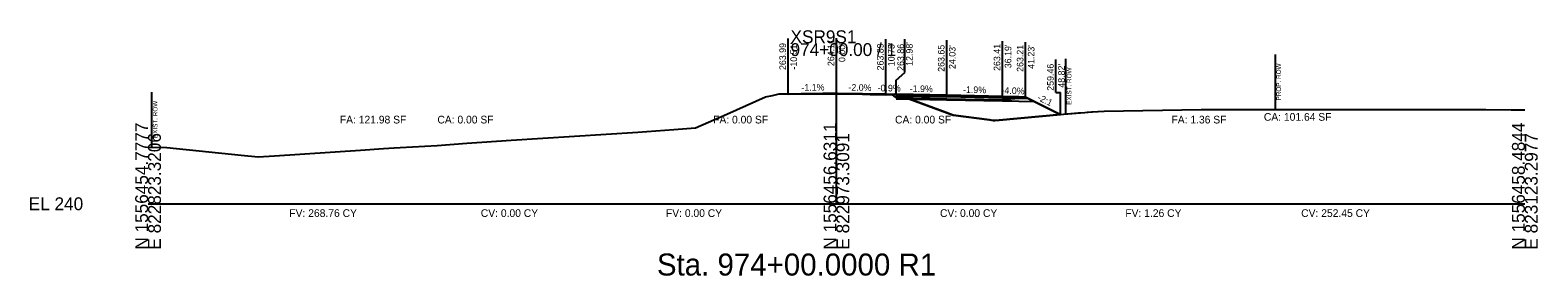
# Model space of a CAD drawing. Extents: x -26 to 823017, y -16 to 1558356.
# Drawn here: x 1974.3 to 2302.8, y 4984.3 to 5037.8 of the extents above; entities that cross this region are included whole.
import ezdxf

# ---------------------------------------------------------------- set-up
doc = ezdxf.new("R2010")
doc.units = 0
for name, color, linetype in [('ASPHALT_19MM1', 7, 'Continuous'), ('CONST_DCH', 7, 'Continuous'), ('CONST_LV3', 7, 'Continuous'), ('Draft_XS_Grid', 7, 'Continuous'), ('Draft_XS_Text', 7, 'Continuous'), ('DTM_CORRIDOR', 7, 'Continuous'), ('DTM_P_FINISHED_GRADE2', 7, 'Continuous'), ('DTM_X_GROUND', 7, 'Continuous'), ('SLOPE_STAKES_FILL', 7, 'Continuous'), ('X_PROFILES_1', 7, 'Continuous'), ('X_TRANS_EOP', 7, 'Continuous'), ('XS_CELL', 7, 'Continuous'), ('XS_P_ASPHALT', 7, 'Continuous'), ('XS_P_DR_GRAVEL', 7, 'Continuous'), ('XS_P_GROUND', 7, 'Continuous'), ('XS_P_NULL_POINT', 7, 'Continuous'), ('XS_P_ROW', 7, 'Continuous'), ('XS_P_SHOULDER', 7, 'Continuous'), ('XS_P_SUBGRADE_GRANULAR', 7, 'Continuous'), ('XS_P_SUBGRADE_LEVELING', 7, 'Continuous'), ('XS_P_SUBGRADE_MILLING', 7, 'Continuous'), ('XS_P_SUBGRADE_UNDERCUT', 7, 'Continuous'), ('XS_P_TX_CLEARZONE', 7, 'Continuous'), ('XS_P_TX_FS_BS', 7, 'Continuous'), ('XS_SHEET_EW_TX_AREA', 7, 'Continuous'), ('XS_SHEET_EW_TX_VOLUME', 7, 'Continuous'), ('XS_X_ROW', 7, 'Continuous')]:
    doc.layers.add(name, color=color, linetype=linetype)

msp = doc.modelspace()

# ---------------------------------------------------------------- linework, layer by layer
at = {"layer": 'ASPHALT_19MM1'}
for points in [[(2162.98, 5023.69), (2162.98, 5023.48), (2174.03, 5023.27), (2174.03, 5023.48), (2162.98, 5023.69)], [(2186.19, 5023.24), (2186.19, 5023.03), (2174.03, 5023.27), (2174.03, 5023.27), (2174.03, 5023.48), (2174.03, 5023.48), (2186.19, 5023.24)]]:
    msp.add_lwpolyline(points, dxfattribs=at)
at = {"layer": 'CONST_LV3'}
for points in [[(2000, 5012.33), (2000, 5012.33), (2004.12, 5012.29), (2020.27, 5010.59), (2024.02, 5010.19), (2027.53, 5010.43), (2046.28, 5011.68), (2051.29, 5012.02), (2053.61, 5012.17), (2054.95, 5012.26), (2063.03, 5012.73), (2069.48, 5013.21), (2072.7, 5013.42), (2079.12, 5013.85), (2106.7, 5015.57), (2114.6, 5016.17), (2119.29, 5016.52), (2126.13, 5019.55), (2134.53, 5023.27), (2136.05, 5023.63), (2137.52, 5023.96), (2139.49, 5023.99), (2139.49, 5023.99)], [(2150, 5024.11), (2164, 5023.83)], [(2160.75, 5023.79), (2160.75, 5023.79), (2162.11, 5023.75), (2162.11, 5023.75), (2162.11, 5023.75), (2162.11, 5023.75), (2162.12, 5023.74), (2162.16, 5023.71), (2162.44, 5023.5), (2162.52, 5023.45), (2162.98, 5023.11), (2162.98, 5023.11), (2174.03, 5022.9), (2174.03, 5022.9), (2186.19, 5022.66), (2187.06, 5022.76), (2189.76, 5023.05), (2190.83, 5023.16), (2191.23, 5023.21), (2192.94, 5022.35), (2198.76, 5019.46), (2198.78, 5019.46), (2198.82, 5019.46), (2199.47, 5019.52), (2200.29, 5019.6), (2202.66, 5019.79), (2204.15, 5019.91), (2204.6, 5019.95), (2205.59, 5020.03), (2205.79, 5020.05), (2208.33, 5020.17), (2229.48, 5020.51), (2274.71, 5020.55), (2291.51, 5020.53), (2297.01, 5020.5), (2300, 5020.47)], [(2162.75, 5023.88), (2164, 5023.83), (2164, 5023.83)], [(2191.25, 5023.2), (2198.81, 5019.46)]]:
    msp.add_lwpolyline(points, dxfattribs=at)
at = {"layer": 'DTM_P_FINISHED_GRADE2'}
msp.add_lwpolyline([(2139.49, 5023.99), (2150, 5024.11), (2160.75, 5023.96)], dxfattribs=at)
at = {"layer": 'DTM_X_GROUND'}
for points in [[(2000, 5012.33), (2000, 5012.33), (2004.12, 5012.29), (2020.27, 5010.59), (2024.02, 5010.19), (2027.53, 5010.43), (2046.28, 5011.68), (2051.29, 5012.02), (2053.61, 5012.17), (2054.95, 5012.26), (2063.03, 5012.73), (2069.48, 5013.21), (2072.7, 5013.42), (2079.12, 5013.85), (2106.7, 5015.57), (2114.6, 5016.17), (2119.29, 5016.52), (2126.13, 5019.55), (2134.53, 5023.27), (2136.05, 5023.63), (2137.52, 5023.96), (2147.12, 5024.07), (2150.24, 5024.11), (2155.68, 5024), (2157.37, 5023.97), (2162.98, 5023.86), (2163.19, 5023.79), (2164.22, 5023.48), (2173.94, 5019.86), (2175.45, 5019.29), (2183.36, 5018.29), (2184.15, 5018.18), (2184.49, 5018.14), (2185.48, 5018.23), (2199.47, 5019.53), (2204.15, 5019.91), (2205.59, 5020.04), (2208.33, 5020.17), (2229.48, 5020.51), (2274.71, 5020.55), (2291.51, 5020.53), (2297.01, 5020.5), (2300, 5020.47)], [(2000, 5012.33), (2000, 5012.33), (2004.12, 5012.29), (2020.27, 5010.59), (2024.02, 5010.19), (2027.53, 5010.43), (2046.28, 5011.68), (2051.29, 5012.02), (2053.61, 5012.17), (2054.95, 5012.26), (2063.03, 5012.73), (2069.48, 5013.21), (2072.7, 5013.42), (2079.12, 5013.85), (2106.7, 5015.57), (2114.6, 5016.17), (2119.29, 5016.52), (2126.13, 5019.55), (2134.53, 5023.27), (2136.05, 5023.63), (2137.52, 5023.96), (2147.12, 5024.07), (2150.24, 5024.11), (2155.68, 5023.96), (2157.37, 5023.91), (2162.11, 5023.75), (2162.11, 5023.75), (2162.11, 5023.75), (2162.11, 5023.75), (2162.12, 5023.74), (2162.16, 5023.71), (2162.44, 5023.5), (2162.52, 5023.45), (2162.98, 5023.11), (2162.98, 5023.11), (2174.03, 5022.9), (2174.03, 5022.9), (2186.19, 5022.66), (2187.06, 5022.76), (2189.76, 5023.05), (2190.83, 5023.16), (2191.23, 5023.21), (2192.94, 5022.35), (2198.76, 5019.46), (2198.78, 5019.46), (2198.82, 5019.46), (2199.47, 5019.52), (2200.29, 5019.6), (2202.66, 5019.79), (2204.15, 5019.91), (2204.6, 5019.95), (2205.59, 5020.03), (2205.79, 5020.05), (2208.33, 5020.17), (2229.48, 5020.51), (2274.71, 5020.55), (2291.51, 5020.53), (2297.01, 5020.5), (2300, 5020.47)], [(2000, 5012.33), (2000, 5012.33), (2004.12, 5012.29), (2020.27, 5010.59), (2024.02, 5010.19), (2027.53, 5010.43), (2046.28, 5011.68), (2051.29, 5012.02), (2053.61, 5012.17), (2054.95, 5012.26), (2063.03, 5012.73), (2069.48, 5013.21), (2072.7, 5013.42), (2079.12, 5013.85), (2106.7, 5015.57), (2114.6, 5016.17), (2119.29, 5016.52), (2126.13, 5019.55), (2134.53, 5023.27), (2136.05, 5023.63), (2137.52, 5023.96), (2139.49, 5023.99), (2139.49, 5023.99), (2150, 5024.11), (2150, 5024.11), (2150, 5024.11), (2150, 5024.11), (2150, 5024.11), (2150, 5024.11), (2150, 5024.11), (2150, 5024.11), (2160.75, 5023.96), (2160.75, 5023.96), (2160.75, 5023.96), (2162.11, 5023.75), (2162.11, 5023.75), (2162.11, 5023.75), (2162.11, 5023.75), (2162.12, 5023.74), (2162.16, 5023.71), (2162.44, 5023.5), (2162.52, 5023.45), (2162.98, 5023.11), (2162.98, 5023.11), (2174.03, 5022.9), (2174.03, 5022.9), (2186.19, 5022.66), (2187.06, 5022.76), (2189.76, 5023.05), (2190.83, 5023.16), (2191.23, 5023.21), (2192.94, 5022.35), (2198.76, 5019.46), (2198.78, 5019.46), (2198.82, 5019.46), (2199.47, 5019.52), (2200.29, 5019.6), (2202.66, 5019.79), (2204.15, 5019.91), (2204.6, 5019.95), (2205.59, 5020.03), (2205.79, 5020.05), (2208.33, 5020.17), (2229.48, 5020.51), (2274.71, 5020.55), (2291.51, 5020.53), (2297.01, 5020.5), (2300, 5020.47)]]:
    msp.add_lwpolyline(points, dxfattribs=at)
at = {"layer": 'X_TRANS_EOP'}
for points in [[(2162.98, 5023.86), (2162.98, 5023.69), (2174.03, 5023.48), (2174.03, 5023.65), (2162.98, 5023.86)], [(2186.19, 5023.41), (2186.19, 5023.24), (2174.03, 5023.48), (2174.03, 5023.48), (2174.03, 5023.65), (2174.03, 5023.65), (2186.19, 5023.41)]]:
    msp.add_lwpolyline(points, dxfattribs=at)
at = {"layer": 'XS_CELL'}
for p, q in [((2150, 5000), (2150, 5035)), ((2000, 5000), (2150, 5000)), ((2150, 5000), (2300, 5000))]:
    msp.add_line(p, q, dxfattribs=at)
at = {"layer": 'XS_P_ASPHALT'}
msp.add_lwpolyline([(2139.49, 5023.99), (2150, 5024.11), (2150, 5024.11), (2160.75, 5023.89), (2160.75, 5023.89), (2160.75, 5023.77), (2160.75, 5023.77), (2150, 5023.98), (2150, 5023.98), (2139.49, 5023.86), (2139.49, 5023.99)], dxfattribs=at)
at = {"layer": 'XS_P_DR_GRAVEL'}
msp.add_lwpolyline([(2191.23, 5023.21), (2191.8, 5022.93), (2189.76, 5022.97), (2186.19, 5023.03), (2186.19, 5023.41), (2189.76, 5023.27), (2191.23, 5023.21)], dxfattribs=at)
at = {"layer": 'XS_P_GROUND'}
for points in [[(2162.8, 5023.86), (2162.75, 5023.88)], [(2198.81, 5019.47), (2198.81, 5019.47), (2198.81, 5019.47), (2185.48, 5018.23), (2185.48, 5018.23), (2184.49, 5018.14), (2184.15, 5018.18), (2183.36, 5018.29), (2183.36, 5018.29), (2175.45, 5019.29), (2175.45, 5019.29), (2173.94, 5019.86), (2173.94, 5019.86), (2164.22, 5023.48), (2164.22, 5023.48), (2164.22, 5023.48), (2163.19, 5023.79), (2163.19, 5023.79), (2162.98, 5023.86), (2162.98, 5023.86), (2162.8, 5023.86)], [(2162.8, 5023.86), (2162.98, 5023.86), (2162.98, 5023.86), (2163.19, 5023.79), (2163.19, 5023.79), (2164.22, 5023.48), (2164.22, 5023.48), (2164.22, 5023.48), (2173.94, 5019.86), (2173.94, 5019.86), (2175.45, 5019.29), (2175.45, 5019.29), (2183.36, 5018.29), (2183.36, 5018.29), (2184.15, 5018.18), (2184.49, 5018.14), (2185.48, 5018.23), (2185.48, 5018.23), (2198.81, 5019.47), (2198.81, 5019.47), (2198.81, 5019.47)], [(2191.23, 5023.21), (2198.82, 5019.46)]]:
    msp.add_lwpolyline(points, dxfattribs=at)
at = {"layer": 'XS_P_ROW'}
msp.add_line((2245.65, 5020.52), (2245.65, 5032.52), dxfattribs=at)
at = {"layer": 'XS_P_SHOULDER'}
msp.add_lwpolyline([(2191.23, 5023.21), (2189.76, 5023.27), (2186.19, 5023.41)], dxfattribs=at)
at = {"layer": 'XS_P_SUBGRADE_GRANULAR'}
for points in [[(2186.19, 5022.37), (2174.03, 5022.6), (2174.03, 5022.6), (2162.98, 5022.82)], [(2193.23, 5022.22), (2189.76, 5022.3), (2188.21, 5022.33), (2186.19, 5022.37)]]:
    msp.add_lwpolyline(points, dxfattribs=at)
at = {"layer": 'XS_P_SUBGRADE_LEVELING'}
for points in [[(2139.49, 5023.86), (2139.49, 5023.86), (2147.12, 5023.95), (2147.12, 5023.95), (2150, 5023.98), (2150.24, 5023.98), (2150.24, 5023.98), (2155.68, 5023.87), (2155.68, 5023.87), (2157.37, 5023.84), (2160.75, 5023.77), (2160.75, 5023.77)], [(2160.75, 5023.77), (2160.75, 5023.77), (2157.37, 5023.84), (2157.37, 5023.84), (2155.68, 5023.87), (2150.24, 5023.98), (2150.24, 5023.98), (2150.24, 5023.98), (2150, 5023.98), (2147.12, 5023.95), (2147.12, 5023.95), (2139.49, 5023.86), (2139.49, 5023.86)]]:
    msp.add_lwpolyline(points, dxfattribs=at)
at = {"layer": 'XS_P_SUBGRADE_MILLING'}
msp.add_lwpolyline([(2160.75, 5023.79), (2160.75, 5023.79), (2160.75, 5023.77), (2160.75, 5023.77), (2157.37, 5023.84), (2157.37, 5023.84), (2155.68, 5023.87), (2150.24, 5023.98), (2150.24, 5023.98), (2150.24, 5023.98), (2150, 5023.98), (2147.12, 5023.95), (2147.12, 5023.95), (2139.49, 5023.86), (2139.49, 5023.86), (2139.49, 5023.99), (2139.49, 5023.99), (2147.12, 5024.07), (2147.12, 5024.07), (2150, 5024.11), (2150.24, 5024.11), (2150.24, 5024.11), (2155.68, 5023.96), (2155.68, 5023.96), (2157.37, 5023.91), (2160.75, 5023.79)], dxfattribs=at)
at = {"layer": 'XS_P_SUBGRADE_UNDERCUT'}
msp.add_lwpolyline([(2162.98, 5023.86), (2175.45, 5019.29), (2184.49, 5018.14), (2191.58, 5018.8), (2198.76, 5019.46), (2191.23, 5023.21), (2189.76, 5023.27), (2186.19, 5023.41), (2174.03, 5023.65)], close=True, dxfattribs=at)
at = {"layer": 'XS_P_TX_CLEARZONE'}
for p, q in [((2139.49, 5023.99), (2139.49, 5035.99)), ((2150, 5024.11), (2150, 5036.11)), ((2160.75, 5023.89), (2160.75, 5035.89)), ((2164.92, 5028.62), (2164.92, 5035.86)), ((2174.03, 5023.65), (2174.03, 5035.65)), ((2186.19, 5023.41), (2186.19, 5035.41)), ((2191.23, 5023.21), (2191.23, 5035.21)), ((2197.83, 5024.28), (2197.83, 5031.46)), ((2162.98, 5026.92), (2164.92, 5028.62)), ((2162.98, 5023.86), (2162.98, 5026.92)), ((2197.83, 5024.28), (2198.82, 5024.28)), ((2198.82, 5019.46), (2198.82, 5024.28))]:
    msp.add_line(p, q, dxfattribs=at)
at = {"layer": 'XS_X_ROW'}
for p, q in [((2200, 5019.57), (2200, 5031.57)), ((2000.84, 5012.32), (2000.84, 5024.32))]:
    msp.add_line(p, q, dxfattribs=at)

# ---------------------------------------------------------------- texts
at = {"layer": 'CONST_DCH'}
for p in [(2139.41, 5023.87), (2149.92, 5023.99), (2160.68, 5023.77)]:
    msp.add_text('X', height=0.24, dxfattribs=at).set_placement(p)
at = {"layer": 'CONST_LV3'}
for p in [(2162.68, 5023.76), (2162.72, 5023.74), (2198.73, 5019.34)]:
    msp.add_text('X', height=0.24, dxfattribs=at).set_placement(p)
at = {"layer": 'Draft_XS_Grid'}
msp.add_text('-', height=0.0001, dxfattribs=at).set_placement((2000, 5000))
at = {"layer": 'Draft_XS_Text'}
msp.add_text('Sta. 974+00.0000 R1', height=4.8, dxfattribs=at).set_placement((2110.88, 4984.35))
at = {"layer": 'DTM_CORRIDOR'}
for p in [(2162.9, 5023.74), (2173.96, 5023.53), (2186.11, 5023.29)]:
    msp.add_text('X', height=0.24, dxfattribs=at).set_placement(p)
at = {"layer": 'SLOPE_STAKES_FILL'}
msp.add_text('X', height=0.24, dxfattribs=at).set_placement((2198.74, 5019.34))
at = {"layer": 'X_PROFILES_1'}
msp.add_text('X', height=0.24, dxfattribs=at).set_placement((2198.73, 5019.34))
at = {"layer": 'XS_CELL'}
for s, p in [('XSR9S1', (2140, 5035)), ('974+00.00 / 1', (2140, 5032.2)), ('EL 240', (1974, 4998.6))]:
    msp.add_text(s, height=2.8, dxfattribs=at).set_placement(p)
for s, p in [('N 1556454.7777', (2000, 4990)), ('N 1556456.6311', (2150, 4990)), ('N 1556458.4844', (2300, 4990)), ('E 822823.3206', (2002.8, 4990)), ('E 822973.3091', (2152.8, 4990)), ('E 823123.2977', (2302.8, 4990))]:
    msp.add_text(s, height=2.8, rotation=90, dxfattribs=at).set_placement(p)
at = {"layer": 'XS_P_NULL_POINT'}
msp.add_text('X', height=0.24, dxfattribs=at).set_placement((2198.74, 5019.34))
at = {"layer": 'XS_P_ROW'}
msp.add_text('PROP. ROW', height=1, rotation=90, dxfattribs=at).set_placement((2246.86, 5022.52))
at = {"layer": 'XS_P_SHOULDER'}
msp.add_text('X', height=0.24, dxfattribs=at).set_placement((2191.15, 5023.09))
at = {"layer": 'XS_P_TX_CLEARZONE'}
for s, p in [('263.99', (2139.01, 5029.15)), ("-10.51'", (2141.41, 5029.25)), ('264.11', (2149.52, 5030.01)), ("0.00'", (2151.92, 5030.89)), ('263.89', (2160.27, 5029.06)), ("10.75'", (2162.67, 5029.98)), ('263.86', (2164.72, 5028.96)), ("12.98'", (2166.61, 5030.06)), ('263.65', (2173.55, 5028.76)), ("24.03'", (2175.95, 5029.37)), ('263.41', (2185.71, 5028.95)), ("36.19'", (2188.11, 5029.54)), ('263.21', (2190.75, 5028.75)), ("41.23'", (2193.15, 5029.41)), ('259.46', (2197.35, 5024.63)), ("48.82'", (2199.75, 5025.3))]:
    msp.add_text(s, height=1.44, rotation=90, dxfattribs=at).set_placement(p)
at = {"layer": 'XS_P_TX_FS_BS'}
for s, rotation, p in [('-1.1%', 0.654, (2142.37, 5024.62)), ('-2.0%', 358.8693, (2152.6, 5024.66)), ('-0.9%', 359.4872, (2158.97, 5024.51)), ('-1.9%', 358.9028, (2165.96, 5024.4)), ('-1.9%', 358.8873, (2177.57, 5024.18)), ('-4.0%', 357.7099, (2185.94, 5024.02)), ('-2:1', 333.7044, (2193.66, 5022.68))]:
    msp.add_text(s, height=1.44, rotation=rotation, dxfattribs=at).set_placement(p)
at = {"layer": 'XS_SHEET_EW_TX_AREA'}
for s, p in [('FA: 121.98 SF', (2041.79, 5017.5)), ('CA: 0.00 SF', (2063.05, 5017.5)), ('FA: 0.00 SF', (2123.13, 5017.5)), ('CA: 0.00 SF', (2162.77, 5017.5)), ('FA: 1.36 SF', (2223, 5017.5)), ('CA: 101.64 SF', (2243.14, 5018.09))]:
    msp.add_text(s, height=1.68, dxfattribs=at).set_placement(p)
at = {"layer": 'XS_SHEET_EW_TX_VOLUME'}
for s, p in [('FV: 268.76 CY', (2030.78, 4997.12)), ('CV: 0.00 CY', (2072.51, 4997.12)), ('FV: 0.00 CY', (2112.85, 4997.12)), ('CV: 0.00 CY', (2172.56, 4997.12)), ('FV: 1.26 CY', (2212.95, 4997.12)), ('CV: 252.45 CY', (2251.27, 4997.12))]:
    msp.add_text(s, height=1.68, dxfattribs=at).set_placement(p)
at = {"layer": 'XS_X_ROW'}
for p in [(2201.2, 5021.57), (2002.04, 5014.32)]:
    msp.add_text('EXIST. ROW', height=1, rotation=90, dxfattribs=at).set_placement(p)

doc.saveas('drawing.dxf')
